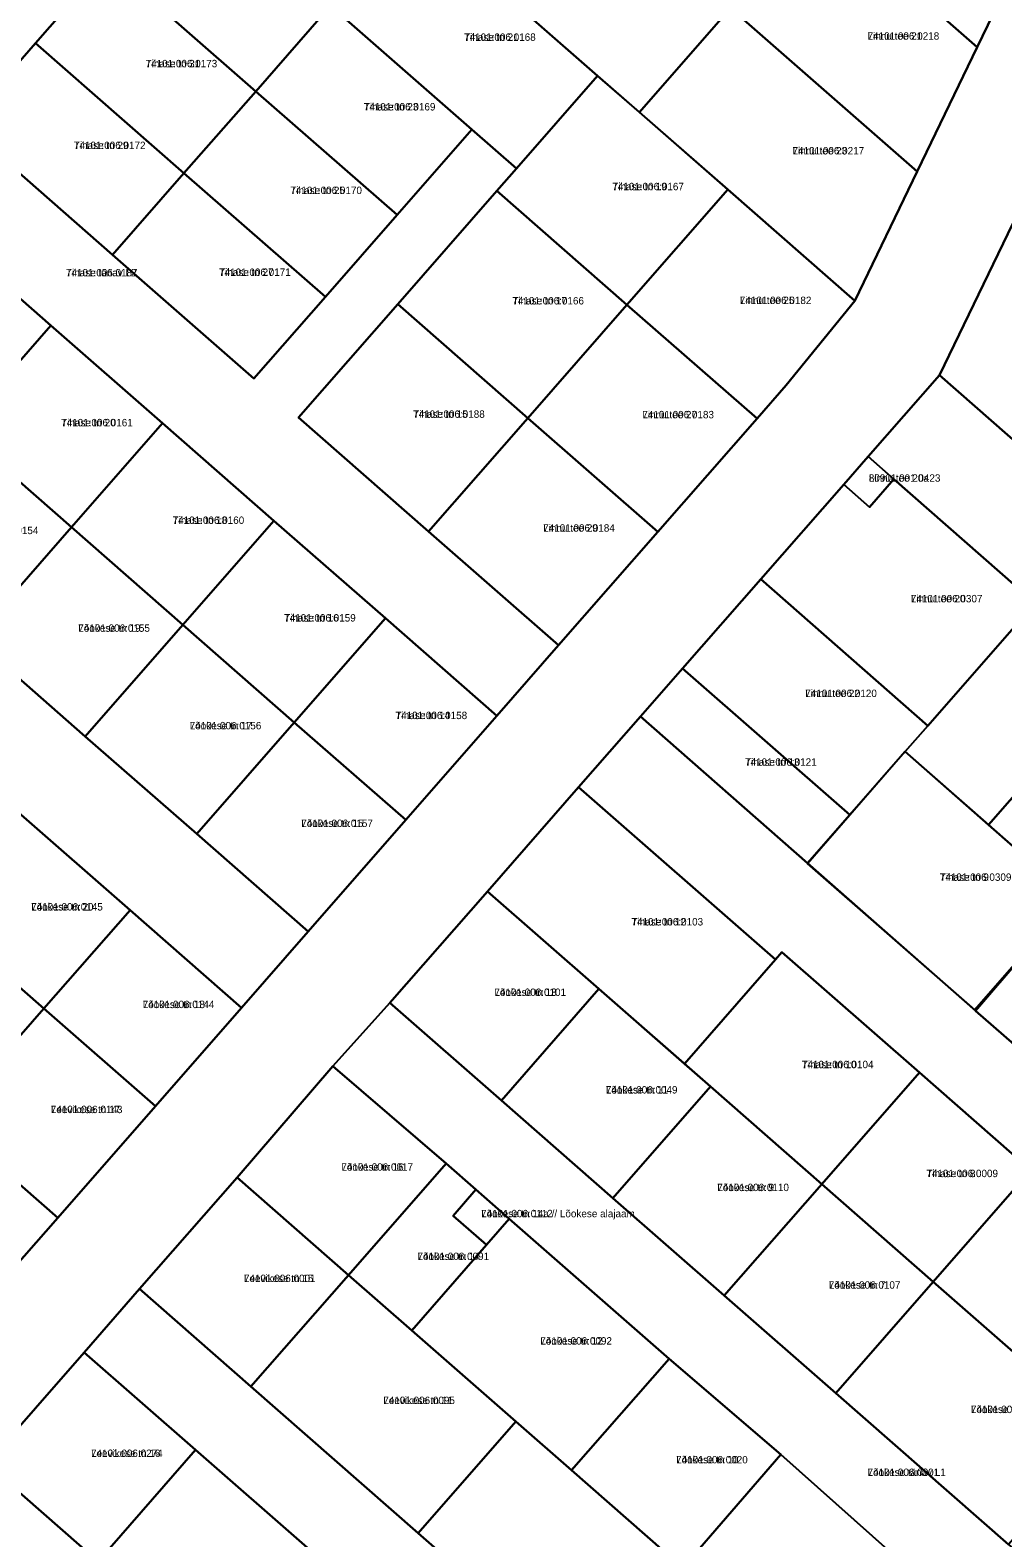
# Model space of a CAD drawing. Extents: x 524000 to 564260, y 6469338 to 6496391.
# Drawn here: x 537011.8 to 537208.8, y 6471813 to 6472118.2 of the extents above; entities that cross this region are included whole.
import ezdxf

# ---------------------------------------------------------------- set-up
doc = ezdxf.new("R2010")
doc.units = 0
for name, color, linetype in [('L_AADRESS', 7, 'Continuous'), ('PIIR', 7, 'Continuous'), ('TUNNUS', 7, 'Continuous')]:
    doc.layers.add(name, color=color, linetype=linetype)

msp = doc.modelspace()

# ---------------------------------------------------------------- linework, layer by layer
at = {"layer": 'PIIR'}
for points in [[(537206.22, 6472167.18), (537222.16, 6472153.23), (537203.58, 6472114.76), (537179.1, 6472136.19)], [(537027.37, 6472132.15), (537042.51, 6472149.44), (537072.6, 6472123.09), (537057.47, 6472105.8)], [(537116.09, 6472151.49), (537121.73, 6472146.55), (537151.61, 6472120.4), (537135.14, 6472101.58), (537126.69, 6472108.97), (537099.61, 6472132.67)], [(537072.6, 6472123.09), (537089.07, 6472141.9), (537126.69, 6472108.97), (537110.23, 6472090.16), (537101.2, 6472098.06)], [(537171.36, 6472142.97), (537179.1, 6472136.19), (537203.58, 6472114.76), (537191.4, 6472089.56), (537153.58, 6472122.65)], [(537012.83, 6472115.57), (537027.37, 6472132.15), (537057.47, 6472105.8), (537042.88, 6472089.21)], [(537057.47, 6472105.8), (537072.6, 6472123.09), (537101.2, 6472098.06), (537086.07, 6472080.77)], [(537153.58, 6472122.65), (537191.4, 6472089.56), (537178.76, 6472063.41), (537153.03, 6472085.92), (537135.14, 6472101.58), (537151.61, 6472120.4)], [(537028.47, 6472072.68), (536998.37, 6472099.05), (537012.83, 6472115.57), (537042.88, 6472089.21)], [(537106.29, 6472085.66), (537110.23, 6472090.16), (537126.69, 6472108.97), (537153.03, 6472085.92), (537132.63, 6472062.61)], [(537042.88, 6472089.21), (537057.47, 6472105.8), (537086.07, 6472080.77), (537071.58, 6472064.22)], [(537028.47, 6472072.68), (537042.88, 6472089.21), (537071.58, 6472064.22), (537057.09, 6472047.67)], [(536883.5, 6472070.02), (536885.55, 6472072.96), (536895.29, 6472086.93), (536925.09, 6472060.84), (536951.43, 6472037.79), (536977.76, 6472014.73), (537000.34, 6471994.98), (537022.91, 6471975.22), (537045.49, 6471955.46), (537068.06, 6471935.7), (537054.57, 6471920.29), (537032, 6471940.05), (537009.42, 6471959.8), (536986.85, 6471979.56), (536964.27, 6471999.32), (536937.94, 6472022.37), (536911.6, 6472045.42)], [(537106.29, 6472085.66), (537132.63, 6472062.61), (537112.54, 6472039.66), (537086.2, 6472062.71)], [(537132.63, 6472062.61), (537153.03, 6472085.92), (537178.76, 6472063.41), (537164.89, 6472046.32), (537158.97, 6472039.56)], [(536971.2, 6472060.38), (536989.64, 6472081.45), (537015.98, 6472058.4), (536997.54, 6472037.33)], [(537210.75, 6472079.08), (537231.22, 6472059.28), (537232.82, 6472057.74), (537213.54, 6472032.88), (537195.93, 6472048.34)], [(537066.12, 6472039.76), (537086.2, 6472062.71), (537112.54, 6472039.66), (537092.45, 6472016.71)], [(537112.54, 6472039.66), (537132.63, 6472062.61), (537158.97, 6472039.56), (537138.88, 6472016.61)], [(536997.54, 6472037.33), (537015.98, 6472058.4), (537038.55, 6472038.64), (537020.11, 6472017.57)], [(537092.45, 6472016.71), (537112.54, 6472039.66), (537138.88, 6472016.61), (537118.79, 6471993.66)], [(536977.76, 6472014.73), (536997.54, 6472037.33), (537020.11, 6472017.57), (537000.34, 6471994.98)], [(537020.11, 6472017.57), (537038.55, 6472038.64), (537061.13, 6472018.88), (537042.69, 6471997.81)], [(537186.69, 6472027.32), (537181.76, 6472021.64), (537176.52, 6472026.23), (537181.45, 6472031.9)], [(537176.52, 6472026.23), (537181.76, 6472021.64), (537186.69, 6472027.32), (537215.33, 6472002.21), (537193.57, 6471977.37), (537159.73, 6472007.01)], [(536854.08, 6472020.68), (536874.39, 6472002.91), (536900.72, 6471979.86), (536927.06, 6471956.81), (536949.64, 6471937.05), (536972.21, 6471917.29), (536994.78, 6471897.53), (537017.36, 6471877.77), (537006.16, 6471864.98), (536855.67, 6471996.71)], [(537042.69, 6471997.81), (537061.13, 6472018.88), (537083.7, 6471999.12), (537065.26, 6471978.05)], [(537000.34, 6471994.98), (537020.11, 6472017.57), (537042.69, 6471997.81), (537022.91, 6471975.22)], [(537143.9, 6471988.99), (537159.73, 6472007.01), (537193.57, 6471977.37), (537188.94, 6471972.13), (537177.75, 6471959.34)], [(537215.33, 6472002.21), (537232.22, 6471987.42), (537205.87, 6471957.31), (537188.94, 6471972.13), (537193.57, 6471977.37)], [(537022.91, 6471975.22), (537042.69, 6471997.81), (537065.26, 6471978.05), (537045.49, 6471955.46)], [(537065.26, 6471978.05), (537083.7, 6471999.12), (537106.28, 6471979.36), (537087.84, 6471958.29)], [(537135.34, 6471979.21), (537143.9, 6471988.99), (537177.75, 6471959.34), (537169.19, 6471949.56)], [(537232.22, 6471987.42), (537249.15, 6471972.6), (537222.8, 6471942.49), (537205.87, 6471957.31)], [(537135.34, 6471979.21), (537169.19, 6471949.56), (537203.24, 6471919.68), (537225.62, 6471900.17), (537248.19, 6471880.41), (537270.76, 6471860.65), (537293.77, 6471840.51), (537284.27, 6471826.25), (537249.42, 6471856.76), (537214.43, 6471887.39), (537191.86, 6471907.15), (537164.02, 6471931.51), (537162.71, 6471930.01), (537122.84, 6471964.92)], [(537045.49, 6471955.46), (537065.26, 6471978.05), (537087.84, 6471958.29), (537068.06, 6471935.7)], [(537169.2, 6471949.51), (537177.78, 6471959.35), (537188.9, 6471972.12), (537205.86, 6471957.3), (537222.8, 6471942.41), (537203.05, 6471919.82)], [(537122.84, 6471964.92), (537162.71, 6471930.01), (537144.27, 6471908.93), (537126.96, 6471924.08), (537104.39, 6471943.84)], [(536991.97, 6471939.86), (537009.42, 6471959.8), (537032, 6471940.05), (537014.54, 6471920.11)], [(537104.39, 6471943.84), (537126.96, 6471924.08), (537107.19, 6471901.5), (537084.62, 6471921.26)], [(537222.8, 6471942.49), (537245.38, 6471922.74), (537225.62, 6471900.17), (537203.24, 6471919.68)], [(536972.21, 6471917.29), (536991.97, 6471939.86), (537014.54, 6471920.11), (536994.78, 6471897.53)], [(537014.54, 6471920.11), (537032, 6471940.05), (537054.57, 6471920.29), (537037.12, 6471900.35)], [(537164.02, 6471931.51), (537191.86, 6471907.15), (537172.1, 6471884.57), (537149.53, 6471904.32), (537144.27, 6471908.93), (537162.71, 6471930.01)], [(537126.96, 6471924.08), (537149.53, 6471904.32), (537129.76, 6471881.75), (537107.19, 6471901.5)], [(537084.62, 6471921.26), (537107.19, 6471901.5), (537129.76, 6471881.75), (537152.34, 6471861.99), (537174.92, 6471842.23), (537209.9, 6471811.6), (537250.71, 6471775.89), (537265.89, 6471762.61), (537288.37, 6471743), (537277.73, 6471729.69), (537260.58, 6471744.66), (537241.2, 6471761.62), (537208.85, 6471789.93), (537186.07, 6471810.02), (537163.78, 6471829.81), (537141.15, 6471849.21), (537108.79, 6471877.53), (537102.02, 6471883.45), (537096, 6471888.72), (537073.06, 6471908.42)], [(536994.78, 6471897.53), (537014.54, 6471920.11), (537037.12, 6471900.35), (537017.36, 6471877.77)], [(537073.06, 6471908.42), (537096, 6471888.72), (537076.24, 6471866.15), (537053.67, 6471885.9)], [(537191.86, 6471907.15), (537214.43, 6471887.39), (537194.67, 6471864.81), (537172.1, 6471884.57)], [(537152.34, 6471861.99), (537129.76, 6471881.75), (537149.53, 6471904.32), (537172.1, 6471884.57)], [(537096, 6471888.72), (537102.02, 6471883.45), (537097.41, 6471878.18), (537104.18, 6471872.26), (537089.03, 6471854.95), (537076.24, 6471866.15)], [(537214.43, 6471887.39), (537249.42, 6471856.76), (537229.66, 6471834.18), (537194.67, 6471864.81)], [(537053.67, 6471885.9), (537076.24, 6471866.15), (537056.48, 6471843.57), (537033.91, 6471863.34)], [(537172.1, 6471884.57), (537194.67, 6471864.81), (537174.92, 6471842.23), (537152.34, 6471861.99)], [(537102.02, 6471883.45), (537108.79, 6471877.53), (537104.18, 6471872.26), (537097.41, 6471878.18)], [(537089.03, 6471854.95), (537104.18, 6471872.26), (537108.79, 6471877.53), (537141.15, 6471849.21), (537121.39, 6471826.63), (537110.1, 6471836.51)], [(537089.03, 6471854.95), (537110.1, 6471836.51), (537090.34, 6471813.93), (537056.48, 6471843.57), (537076.24, 6471866.15)], [(537033.91, 6471863.34), (537056.48, 6471843.57), (537090.34, 6471813.93), (537124.2, 6471784.29), (537146.77, 6471764.53), (537184.39, 6471731.61), (537205.46, 6471713.17), (537194.51, 6471700.07), (537165.16, 6471725.77), (537135.55, 6471751.69), (537112.98, 6471771.45), (537090.41, 6471791.22), (537067.84, 6471810.98), (537045.26, 6471830.74), (537022.7, 6471850.49)], [(537194.67, 6471864.81), (537229.66, 6471834.18), (537209.9, 6471811.6), (537174.92, 6471842.23)], [(537022.7, 6471850.49), (537045.26, 6471830.74), (537025.51, 6471808.17), (537002.94, 6471827.91)], [(537141.15, 6471849.21), (537163.78, 6471829.81), (537143.96, 6471806.87), (537121.39, 6471826.63)], [(537121.39, 6471826.63), (537143.96, 6471806.87), (537124.2, 6471784.29), (537090.34, 6471813.93), (537110.1, 6471836.51)], [(537045.26, 6471830.74), (537067.84, 6471810.98), (537048.08, 6471788.4), (537025.51, 6471808.17)], [(537163.78, 6471829.81), (537186.07, 6471810.02), (537166.53, 6471787.11), (537143.96, 6471806.87)], [(537002.94, 6471827.91), (537025.51, 6471808.17), (537005.76, 6471785.59), (536983.19, 6471805.36)]]:
    msp.add_lwpolyline(points, close=True, dxfattribs=at)
for points in [[(536952.15, 6471803.3), (537006.16, 6471864.98), (537017.36, 6471877.77), (537037.12, 6471900.35), (537054.57, 6471920.29), (537068.06, 6471935.7), (537087.84, 6471958.29), (537106.28, 6471979.36), (537118.79, 6471993.66), (537138.88, 6472016.61), (537158.97, 6472039.56), (537164.89, 6472046.32), (537178.76, 6472063.41), (537191.4, 6472089.56), (537203.58, 6472114.76), (537222.16, 6472153.23)], [(537027.37, 6472132.15), (537012.83, 6472115.57), (536998.37, 6472099.05), (537028.47, 6472072.68), (537057.09, 6472047.67), (537071.58, 6472064.22), (537086.07, 6472080.77), (537101.2, 6472098.06), (537110.23, 6472090.16), (537106.29, 6472085.66), (537086.2, 6472062.71), (537066.12, 6472039.76), (537092.45, 6472016.71), (537118.79, 6471993.66), (537106.28, 6471979.36), (537083.7, 6471999.12), (537061.13, 6472018.88), (537038.55, 6472038.64), (537015.98, 6472058.4), (536989.64, 6472081.45), (536963.31, 6472104.5), (536936.97, 6472127.55)], [(537230.56, 6472120.27), (537223.01, 6472104.37), (537210.75, 6472079.08), (537195.93, 6472048.34), (537181.45, 6472031.9), (537176.52, 6472026.23), (537159.73, 6472007.01), (537143.9, 6471988.99), (537135.34, 6471979.21), (537122.84, 6471964.92), (537104.39, 6471943.84), (537084.62, 6471921.26), (537073.06, 6471908.42), (537053.67, 6471885.9), (537033.91, 6471863.34), (537022.7, 6471850.49), (537002.94, 6471827.91), (536983.19, 6471805.36)], [(537215.33, 6472002.21), (537186.69, 6472027.32), (537181.45, 6472031.9), (537195.93, 6472048.34), (537213.54, 6472032.88)]]:
    msp.add_lwpolyline(points, dxfattribs=at)

# ---------------------------------------------------------------- texts
at = {"layer": 'L_AADRESS'}
for s, p in [('Tihase tn 21', (537099.65, 6472116.03)), ('Linnu tee 21', (537181.37, 6472116.26)), ('Tihase tn 31', (537035.15, 6472110.68)), ('Tihase tn 23', (537079.34, 6472101.93)), ('Tihase tn 29', (537020.63, 6472094.12)), ('Linnu tee 23', (537166.17, 6472093.03)), ('Tihase tn 25', (537064.46, 6472085.01)), ('Tihase tn 19', (537129.66, 6472085.79)), ('Tihase tänav L2', (537019.02, 6472068.35)), ('Tihase tn 27', (537050.03, 6472068.44)), ('Tihase tn 17', (537109.42, 6472062.66)), ('Linnu tee 25', (537155.48, 6472062.74)), ('Tihase tn 20', (537018.04, 6472037.99)), ('Tihase tn 15', (537089.33, 6472039.71)), ('Linnu tee 27', (537135.75, 6472039.61)), ('Linnu tee 20a', (537181.61, 6472026.77)), ('Tihase tn 18', (537040.62, 6472018.23)), ('Linnu tee 29', (537115.67, 6472016.66)), ('Linnu tee 20', (537190.12, 6472002.35)), ('Tihase tn 16', (537063.2, 6471998.46)), ('Lõokese tn 19', (537021.52, 6471996.39)), ('Linnu tee 22', (537168.74, 6471983.18)), ('Lõokese tn 17', (537044.08, 6471976.64)), ('Tihase tn 14', (537085.77, 6471978.71)), ('Tihase tn 13', (537156.55, 6471969.27)), ('Lõokese tn 15', (537066.67, 6471956.87)), ('Tihase tn 9', (537195.99, 6471945.97)), ('Lõokese tn 20', (537011.98, 6471939.96)), ('Tihase tn 12', (537133.55, 6471936.93)), ('Lõokese tn 13', (537105.79, 6471922.67)), ('Lõokese tn 18', (537034.56, 6471920.2)), ('Tihase tn 10', (537168.06, 6471908.04)), ('Lõokese tn 11', (537128.36, 6471902.91)), ('Leevikese tn 17', (537015.95, 6471898.94)), ('Lõokese tn 16', (537074.8, 6471887.29)), ('Tihase tn 8', (537193.27, 6471885.98)), ('Lõokese tn 9', (537150.93, 6471883.15)), ('Lõokese tn 14a // Lõokese alajaam', (537103.1, 6471877.86)), ('Lõokese tn 14', (537090.21, 6471869.2)), ('Leevikese tn 15', (537055.07, 6471864.74)), ('Lõokese tn 7', (537173.51, 6471863.4)), ('Lõokese tn 12', (537115.09, 6471852.08)), ('Leevikese tn 11', (537083.29, 6471840.04)), ('Lõokese tn 5', (537202.29, 6471838.21)), ('Leevikese tn 16', (537024.1, 6471829.33)), ('Lõokese tn 10', (537142.59, 6471828.03)), ('Lõokese tänav L1', (537181.36, 6471825.48))]:
    msp.add_text(s, height=1.5, dxfattribs=at).set_placement(p)
at = {"layer": 'TUNNUS'}
for s, p in [('74101:006:0168', (537099.65, 6472116.03)), ('74101:006:0218', (537181.37, 6472116.26)), ('74101:006:0173', (537035.15, 6472110.68)), ('74101:006:0169', (537079.34, 6472101.93)), ('74101:006:0172', (537020.63, 6472094.12)), ('74101:006:0217', (537166.17, 6472093.03)), ('74101:006:0170', (537064.46, 6472085.01)), ('74101:006:0167', (537129.66, 6472085.79)), ('74101:006:0187', (537019.02, 6472068.35)), ('74101:006:0171', (537050.03, 6472068.44)), ('74101:006:0166', (537109.42, 6472062.66)), ('74101:006:0182', (537155.48, 6472062.74)), ('74101:006:0161', (537018.04, 6472037.99)), ('74101:006:0188', (537089.33, 6472039.71)), ('74101:006:0183', (537135.75, 6472039.61)), ('80901:001:0423', (537181.61, 6472026.77)), ('74101:006:0160', (537040.62, 6472018.23)), ('74101:006:0184', (537115.67, 6472016.66)), ('74101:006:0154', (536998.93, 6472016.16)), ('74101:006:0307', (537190.12, 6472002.35)), ('74101:006:0159', (537063.2, 6471998.46)), ('74101:006:0155', (537021.52, 6471996.39)), ('74101:006:0120', (537168.74, 6471983.18)), ('74101:006:0158', (537085.77, 6471978.71)), ('74101:006:0156', (537044.08, 6471976.64)), ('74101:006:0121', (537156.55, 6471969.27)), ('74101:006:0157', (537066.67, 6471956.87)), ('74101:006:0309', (537195.99, 6471945.97)), ('74101:006:0145', (537011.98, 6471939.96)), ('74101:006:0103', (537133.55, 6471936.93)), ('74101:006:0101', (537105.79, 6471922.67)), ('74101:006:0144', (537034.56, 6471920.2)), ('74101:006:0104', (537168.06, 6471908.04)), ('74101:006:0049', (537128.36, 6471902.91)), ('74101:006:0143', (537015.95, 6471898.94)), ('74101:006:0017', (537074.8, 6471887.29)), ('74101:006:0009', (537193.27, 6471885.98)), ('74101:006:0110', (537150.93, 6471883.15)), ('74101:006:0112', (537103.1, 6471877.86)), ('74101:006:0091', (537090.21, 6471869.2)), ('74101:006:0001', (537055.07, 6471864.74)), ('74101:006:0107', (537173.51, 6471863.4)), ('74101:006:0092', (537115.09, 6471852.08)), ('74101:006:0095', (537083.29, 6471840.04)), ('74101:006:0108', (537202.29, 6471838.21)), ('74101:006:0274', (537024.1, 6471829.33)), ('74101:006:0020', (537142.59, 6471828.03)), ('74101:006:0301', (537181.36, 6471825.48))]:
    msp.add_text(s, height=1.5, dxfattribs=at).set_placement(p)

doc.saveas('drawing.dxf')
